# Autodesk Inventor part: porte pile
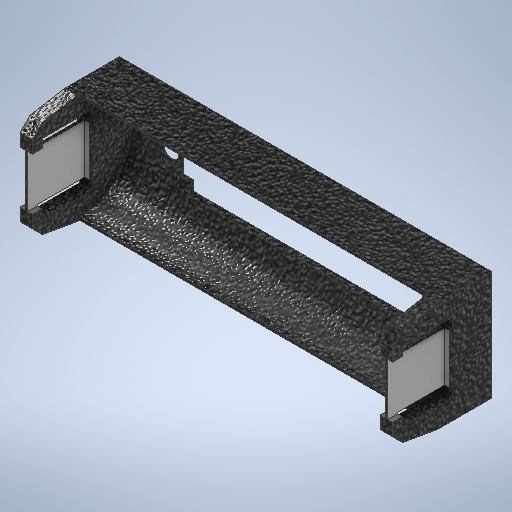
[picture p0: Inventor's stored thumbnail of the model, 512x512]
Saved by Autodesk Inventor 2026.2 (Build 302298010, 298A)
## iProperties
Created: 2026-09
Part Number: porte pile
Material: Générique
Document SubType Name: Modeling
Designer: mel
Density: 1 g/cm^3
Appearance: Moulé noir
Author: mel
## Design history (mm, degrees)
sketch "Esquisse1"
  geometry: L1 (0, 0)-(75, 0); L2 (75, 0)-(75, -22); L3 (75, -22)-(0, -22); L4 (0, -22)-(0, 0)
  constraints: 8 end point, 2 parallel, 1 horizontal, 1 perpendicular
  dimensions: "d0" = 22 distance between parallel lines of L3 L1; "d3" = 75 distance between parallel lines of L2 L4
extrude "Extrusion1" new body sketch "Esquisse1" distance "d1" = 20; taper "d2" = 0 deg
sketch "Esquisse2"
  geometry: L1 (-18, 1.234)-(-11, 0); L2 (-20, 18.766)-(-18, 20.766); L3 (0, 0)-(-20, 0) reference; L4 (0, 22)-(-20, 22) reference; L5 (0, 0)-(0, 22) reference; L6 (-20, 0)-(-20, 22) reference; L7 (-18, 1.234)-(-20, 3.234); L8 (-18, 20.766)-(-11, 22); L9 (-11, 0)-(-20, 0); L10 (-20, 0)-(-20, 22); L11 (-20, 22)-(-11, 22); L12 (-11, 22)-(-11, 0)
  constraints: 16 end point, 4 point on line, 2 parallel, 1 horizontal, 1 perpendicular
  dimensions: "d5" = 45 deg angle of L4 L2 (= d4); "d6" = 10 deg angle of L3 L1; "d8" = 11 distance from line of L1.end L5; "d9" = 2 distance from line of L1.start L6; "d10" = 11 distance from line of L8.end L5 (= d8); "d11" = 2 distance from line of L2.end L6 (= d9); "d12" = 19.53142 distance of L1.start L2.end (derived)
extrude "Extrusion2" cut sketch "Esquisse2" extent not by distance; stored distance "d13" = 0; taper "d14" = 0 deg
sketch "Esquisse3"
  geometry: L1 (75, 20)-(0, 20) reference; L2 (2.5, 20)-(72.5, 20); L3 (72.5, 20)-(72.5, 10.5); L4 (72.5, 10.5)-(2.5, 10.5); L5 (2.5, 10.5)-(2.5, 20); L6 (0, 0)-(0, 11) reference; L7 (75, 18)-(75, 11) reference; L8 (0, 0)-(75, 0) reference; 1 further point
  constraints: 8 end point, 2 parallel, 1 horizontal, 1 perpendicular, 1 point on line
  dimensions: "d15" = 2.5 distance between parallel lines of L5 L6; "d16" = 2.5 distance between parallel lines of L7 L3; "d17" = 10.5 distance between parallel lines of L8 L4
extrude "Extrusion3" cut sketch "Esquisse3" extent not by distance; stored distance "d18" = 0; taper "d19" = 0 deg
sketch "Esquisse4"
  geometry: L1 (0, 21)-(0, 22); L2 (0, 21.5)-(70, 21.5); L3 (70, 21.5)-(70, 11); L4 (70, 11)-(0, 11); L5 (0, 11)-(0, 21.5); L6 (70, 18.766)-(70, 3.234); L7 (0, 22)-(70, 22) reference; 2 further points
  constraints: 12 end point, 1 midpoint
  dimensions: "d20" = 0.5 distance between parallel lines of L7 L2; "d21" = 11 distance between parallel lines of L4 L7
revolve "Révolution1" sketch "Esquisse4" stored, may be unused: angle "d22" = 90 deg
sketch "Esquisse5"
  geometry: L1 (18, 18)-(8, 18); L2 (8, 18)-(8, 16); L3 (8, 16)-(18, 16); L4 (18, 16)-(18, 18); L5 (18, 6)-(8, 6); L6 (8, 6)-(8, 4); L7 (8, 4)-(18, 4); L8 (18, 4)-(18, 6); L9 (0, 22)-(11, 22) reference; L10 (0, 0)-(11, 0) reference; L11 (0, 22)-(0, 0) reference
  constraints: 16 end point, 4 parallel, 2 horizontal, 2 perpendicular, 2 point on line
  dimensions: "d23" = 2 distance between parallel lines of L5 L7; "d24" = 2 distance between parallel lines of L3 L1 (= d23); "d25" = 6 distance between parallel lines of L3 L9; "d26" = 6 distance between parallel lines of L5 L10; "d27" = 10 distance between parallel lines of L2 L4; "d28" = 8 distance between parallel lines of L11 L6
extrude "Extrusion4" cut sketch "Esquisse5" extent not by distance; stored distance "d29" = 0; taper "d30" = 0 deg
sketch "Esquisse6"
  geometry: L1 (20, 3.234)-(20, 18.766) reference; L2 (20, 16.25)-(8.5, 16.25); L3 (8.5, 16.25)-(8.5, 5.75); L4 (8.5, 5.75)-(20, 5.75); L5 (20, 5.75)-(20, 16.25); L6 (8, 18)-(18, 18) reference; L7 (18, 4)-(8, 4) reference; L8 (0, 22)-(0, 0) reference; 1 further point
  constraints: 8 end point, 2 parallel, 1 horizontal, 1 perpendicular, 1 point on line
  dimensions: "d31" = 10.5 distance between parallel lines of L4 L2; "d32" = 1.75 distance between parallel lines of L2 L6; "d33" = 1.75 distance between parallel lines of L4 L7 (derived); "d34" = 8.5 distance between parallel lines of L8 L3
extrude "Extrusion5" cut sketch "Esquisse6" distance "d35" = 1; taper "d36" = 0 deg
sketch "Esquisse7"
  geometry: L1 (11.5, 12.766)-(2, 12.766) reference; L2 (11.5, 2.766)-(11.5, 12.766) reference; L3 (2, 2.766)-(11.5, 2.766) reference; L4 (2, 2.516)-(2, 2.766) reference; L5 (0, 2.516)-(2, 2.516) reference; L6 (0, 13.016)-(0, 2.516) reference; L7 (2, 13.016)-(0, 13.016) reference; L8 (2, 12.766)-(2, 13.016) reference; 1 further point
extrude "Extrusion6" cut sketch "Esquisse7" distance "d37" = 1; taper "d38" = 0 deg
sketch "Esquisse8"
  geometry: L1 (-18, 16.25)-(-18, 16) reference; L2 (-20, 16.25)-(-18, 16.25) reference; L3 (-20, 5.75)-(-20, 16.25) reference; L4 (-18, 5.75)-(-20, 5.75) reference; L5 (-18, 6)-(-18, 5.75) reference; L6 (-8.5, 6)-(-18, 6) reference; L7 (-8.5, 16)-(-8.5, 6) reference; L8 (-18, 16)-(-8.5, 16) reference; 1 further point
extrude "Extrusion7" cut sketch "Esquisse8" distance "d39" = 1; taper "d40" = 0 deg
sketch "Esquisse9"
  geometry: L1 (-11.5, 12.766)-(-2, 12.766) reference; L2 (-11.5, 2.766)-(-11.5, 12.766) reference; L3 (-2, 2.766)-(-11.5, 2.766) reference; L4 (-2, 2.516)-(-2, 2.766) reference; L5 (0, 2.516)-(-2, 2.516) reference; L6 (0, 13.016)-(0, 2.516) reference; L7 (-2, 13.016)-(0, 13.016) reference; L8 (-2, 12.766)-(-2, 13.016) reference; 1 further point
extrude "Extrusion8" cut sketch "Esquisse9" distance "d41" = 1; taper "d42" = 0 deg
sketch "Esquisse10"
  geometry: L1 (-61, -6)-(-15, -6); L2 (-15, -6)-(-15, -16); L3 (-15, -16)-(-61, -16); L4 (-61, -16)-(-61, -6); L5 (-75, -22)-(-75, 0) reference; L6 (0, 0)-(0, -22) reference; L7 (-75, 0)-(0, 0) reference; L8 (0, -22)-(-75, -22) reference; L9 (-15, -8)-(-13, -8); L10 (-13, -8)-(-13, -14); L11 (-13, -14)-(-15, -14); L12 (-15, -14)-(-15, -8); 1 further point
  constraints: 16 end point, 4 parallel, 2 horizontal, 2 perpendicular, 1 point on line
  dimensions: "d43" = 14 distance between parallel lines of L4 L5; "d44" = 15 distance between parallel lines of L6 L2; "d45" = 10 distance between parallel lines of L3 L1; "d46" = 6 distance between parallel lines of L7 L1; "d47" = 6 distance between parallel lines of L8 L3 (derived); "d48" = 2 distance between parallel lines of L10 L2; "d49" = 2 distance between parallel lines of L9 L1; "d50" = 2 distance between parallel lines of L11 L3 (= d49)
extrude "Extrusion9" cut sketch "Esquisse10" extent not by distance; stored distance "d51" = 0; taper "d52" = 0 deg
sketch "Esquisse11"
  geometry: L1 (-2.5, -11)-(-13, -11) reference; L2 (-75, -22)-(-75, 0) reference; L3 (0, 0)-(0, -22) reference; C1 r 1.5 at (-64.5, -11.109); C2 r 1.5 at (-10.5, -11)
  constraints: 2 centre point, 1 point on line
  dimensions: "d53" = 3 diameter of C1; "d54" = 3 diameter of C2; "d55" = 54 horizontal distance of C2.centre C1.centre; "d56" = 10.5 distance from line of C1.centre L2; "d57" = 10.5 distance from line of L3 C2.centre (derived)
extrude "Extrusion10" cut sketch "Esquisse11" extent not by distance; stored distance "d58" = 0; taper "d59" = 0 deg
sketch "Esquisse12"
  geometry: C1 r 1.5 at (62, 10.891); C2 r 1.491 at (8.009, 11); C3 r 2.5 at (62, 10.891); C4 r 2.5 at (8.009, 11); A1 r 1.5 centre (62, 10.891) between (63.496, 11) and (60.504, 11) reference; 3 further points
  constraints: 4 centre point, 4 horizontal alignment, 2 coincident, 3 other
  dimensions: "d60" = 5 diameter of C3; "d61" = 5 diameter of C4
extrude "Extrusion11" cut sketch "Esquisse12" distance "d62" = 10.3; taper "d63" = 0 deg
node "Solide1"
node "Boucle projetée1"
node "Boucle projetée2"
node "Boucle projetée3"
other parameters: "d4" = 45 deg, "d7" = 10 deg (= d6)
